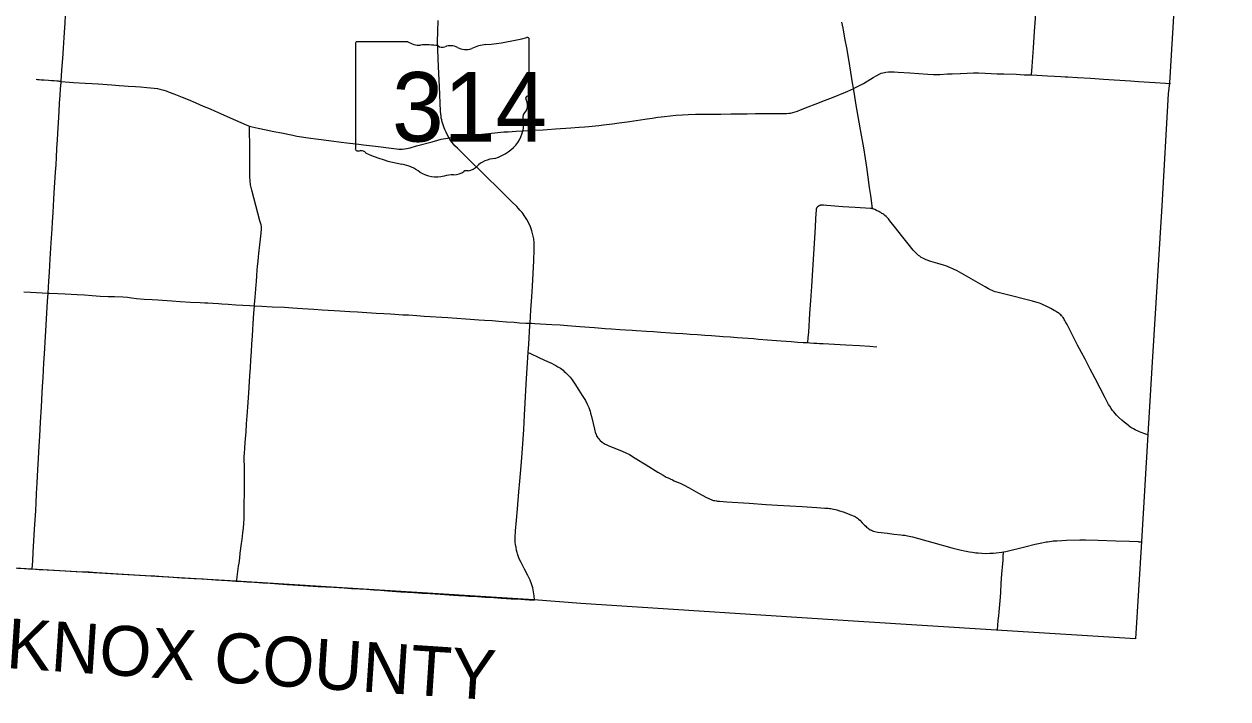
# Model space of a CAD drawing. Extents: x 9078 to 9739, y 4248 to 4966.
# Drawn here: x 9527 to 9647.5, y 4264.9 to 4332.5 of the extents above; entities that cross this region are included whole.
import ezdxf

# ---------------------------------------------------------------- set-up
doc = ezdxf.new("R2010")
doc.units = 0
for name, color, linetype in [('GM_X_Adjacent_County_Text', 7, 'Continuous'), ('GM_X_County', 7, 'Continuous'), ('GM_X_County_Road', 7, 'Continuous'), ('GM_X_State_Route', 7, 'Continuous'), ('GM_X_State_Shield', 7, 'Continuous'), ('GM_X_Township_Road', 7, 'Continuous')]:
    doc.layers.add(name, color=color, linetype=linetype)

msp = doc.modelspace()

# ---------------------------------------------------------------- linework, layer by layer
at = {"layer": 'GM_X_County'}
msp.add_lwpolyline([(9647.55, 4428.55), (9647.41, 4425.74), (9646.56, 4403.19), (9646.56, 4403.07), (9644.94, 4380.52), (9644.77, 4377.86), (9644.66, 4376.07), (9644.25, 4369.41), (9641.71, 4326.63), (9641.57, 4325.53), (9640.94, 4314.3), (9639.94, 4298.12), (9639.53, 4291.39), (9638.88, 4280.68), (9638.29, 4270.92), (9624.37, 4271.81), (9610.55, 4272.68), (9582.74, 4274.46), (9578.04, 4274.83), (9548.2, 4276.71), (9527.73, 4277.92), (9504.96, 4279.33)], dxfattribs=at)
at = {"layer": 'GM_X_County_Road'}
for points in [[(9627.89, 4327.41), (9627.95, 4328.25), (9628.07, 4330.13), (9628.17, 4331.76), (9628.26, 4333.07), (9628.3, 4333.81), (9628.36, 4334.79), (9628.44, 4336.1), (9628.53, 4337.65), (9628.58, 4338.47), (9628.64, 4339.36), (9628.72, 4340.67), (9628.83, 4342.39), (9628.9, 4343.7), (9628.96, 4344.76), (9629.07, 4346.31), (9629.14, 4347.38)], [(9530.7, 4326.77), (9530.74, 4327.4), (9530.8, 4328.29), (9530.86, 4329.07), (9530.92, 4330.09), (9530.99, 4331.16), (9531.03, 4331.65), (9531.1, 4332.63), (9531.15, 4333.37), (9531.19, 4334.11), (9531.22, 4334.59), (9531.28, 4335.82), (9531.33, 4336.64), (9531.36, 4337.29), (9531.38, 4337.7), (9531.39, 4337.88)], [(9610.05, 4326.04), (9610.59, 4326.33), (9611.04, 4326.57), (9612.02, 4327.16), (9612.38, 4327.36), (9612.68, 4327.51), (9612.83, 4327.58), (9612.98, 4327.63), (9613.14, 4327.67), (9613.3, 4327.7), (9613.55, 4327.73), (9613.79, 4327.73), (9614.12, 4327.73), (9614.53, 4327.7), (9615.68, 4327.62), (9616.58, 4327.55), (9617.48, 4327.49), (9618.06, 4327.46), (9618.41, 4327.45), (9618.71, 4327.46), (9619.45, 4327.51), (9619.94, 4327.53), (9620.73, 4327.57), (9620.76, 4327.57), (9621.42, 4327.6), (9622.08, 4327.61), (9622.57, 4327.61), (9623.22, 4327.59), (9624.45, 4327.54), (9625.11, 4327.52), (9626.34, 4327.48), (9627.15, 4327.44), (9627.89, 4327.41)], [(9627.89, 4327.41), (9629.47, 4327.33), (9630.19, 4327.29), (9630.8, 4327.26), (9631.24, 4327.23), (9631.51, 4327.22), (9632.48, 4327.16), (9633.78, 4327.09), (9635.09, 4327), (9637.78, 4326.83), (9638.59, 4326.77), (9640.27, 4326.67), (9641.3, 4326.59), (9641.79, 4326.55)], [(9529.39, 4305.57), (9529.48, 4306.77), (9529.53, 4307.67), (9529.61, 4308.98), (9529.7, 4310.59), (9529.79, 4312.01), (9529.83, 4312.67), (9529.89, 4313.65), (9529.93, 4314.3), (9529.97, 4314.96), (9530.01, 4315.61), (9530.14, 4317.66), (9530.19, 4318.4), (9530.23, 4319.13), (9530.28, 4320.03), (9530.34, 4320.93), (9530.4, 4322.16), (9530.42, 4322.57), (9530.46, 4323.22), (9530.49, 4323.71), (9530.54, 4324.62), (9530.59, 4325.35), (9530.64, 4326.01), (9530.69, 4326.66), (9530.7, 4326.77)], [(9601.7, 4323.55), (9602.27, 4323.55), (9603.01, 4323.54), (9603.33, 4323.55), (9603.58, 4323.58), (9603.74, 4323.6), (9603.98, 4323.65), (9604.21, 4323.72), (9604.44, 4323.79), (9604.75, 4323.91), (9605.51, 4324.22), (9606.2, 4324.48), (9607.14, 4324.85), (9607.96, 4325.17), (9609.26, 4325.69), (9610.03, 4326.03), (9610.05, 4326.04)], [(9569.54, 4321.12), (9569.83, 4321.16), (9570.1, 4321.19), (9572.83, 4321.47), (9574.14, 4321.61), (9575.04, 4321.7), (9575.45, 4321.73), (9576.27, 4321.77), (9578.07, 4321.87), (9578.97, 4321.93), (9579.38, 4321.95), (9580.2, 4322.01), (9581.75, 4322.12), (9582.57, 4322.17), (9583.14, 4322.22), (9583.55, 4322.26), (9584.53, 4322.35), (9585.02, 4322.4), (9585.92, 4322.52), (9586.57, 4322.61), (9587.38, 4322.73), (9588.27, 4322.86), (9589.16, 4323), (9589.9, 4323.1), (9590.46, 4323.18), (9591.12, 4323.26), (9591.69, 4323.33), (9592.26, 4323.39), (9592.91, 4323.43), (9593.49, 4323.46), (9594.23, 4323.49), (9595.29, 4323.5), (9595.95, 4323.5), (9596.77, 4323.5), (9597.75, 4323.52), (9599.4, 4323.53), (9600.22, 4323.55), (9600.95, 4323.55), (9601.7, 4323.55)], [(9526.97, 4305.69), (9527.64, 4305.66), (9528.23, 4305.63), (9528.79, 4305.6), (9529.39, 4305.57)], [(9527.79, 4277.93), (9527.85, 4278.7), (9527.9, 4279.6), (9528.04, 4281.89), (9528.15, 4283.77), (9528.19, 4284.51), (9528.24, 4285.49), (9528.3, 4286.56), (9528.37, 4287.87), (9528.43, 4289.01), (9528.5, 4290.24), (9528.56, 4291.24), (9528.64, 4292.62), (9528.73, 4294.17), (9528.81, 4295.56), (9528.84, 4296.22), (9528.9, 4297.12), (9528.94, 4297.85), (9528.98, 4298.59), (9529.03, 4299.49), (9529.14, 4301.21), (9529.18, 4301.78), (9529.2, 4302.36), (9529.27, 4303.58), (9529.34, 4304.73), (9529.39, 4305.55), (9529.39, 4305.57)], [(9529.39, 4305.57), (9529.54, 4305.56), (9530.35, 4305.53), (9531.1, 4305.49), (9532.3, 4305.42), (9533.04, 4305.38), (9533.81, 4305.33), (9534.59, 4305.27), (9535.4, 4305.23), (9536.03, 4305.21), (9536.88, 4305.18), (9537.35, 4305.14), (9537.73, 4305.09), (9538.25, 4305.03), (9539.02, 4304.96), (9539.82, 4304.92), (9540.39, 4304.88), (9541.32, 4304.83), (9541.77, 4304.8), (9542.61, 4304.73), (9543.66, 4304.66), (9544.61, 4304.62), (9545.08, 4304.6), (9545.4, 4304.57), (9545.88, 4304.54), (9546.46, 4304.51), (9546.79, 4304.49), (9547.42, 4304.44), (9548.2, 4304.4), (9548.88, 4304.36), (9549.58, 4304.32), (9550.06, 4304.29)], [(9550.06, 4304.29), (9550.78, 4304.25), (9551.82, 4304.2), (9553.06, 4304.14), (9553.88, 4304.09), (9554.86, 4304.02), (9556.01, 4303.94), (9556.83, 4303.9), (9558.03, 4303.83), (9558.61, 4303.79), (9559.62, 4303.72), (9560.36, 4303.67), (9562.26, 4303.56), (9563.01, 4303.51), (9563.68, 4303.47), (9564.11, 4303.44), (9564.93, 4303.4), (9565.5, 4303.37), (9566.32, 4303.31), (9567.06, 4303.26), (9569.43, 4303.11), (9571.23, 4302.98), (9572.54, 4302.9), (9573.11, 4302.86), (9573.85, 4302.81), (9574.52, 4302.76), (9575.31, 4302.69), (9576.06, 4302.64), (9576.61, 4302.59), (9577.22, 4302.55), (9577.66, 4302.54)], [(9577.48, 4299.6), (9577.63, 4299.53), (9578.6, 4299.09), (9579.42, 4298.7), (9579.79, 4298.53), (9580.03, 4298.41), (9580.25, 4298.3), (9580.34, 4298.25), (9580.45, 4298.19), (9580.58, 4298.11), (9580.7, 4298.03), (9580.84, 4297.94), (9580.96, 4297.83), (9581.09, 4297.72), (9581.21, 4297.61), (9581.42, 4297.4), (9581.66, 4297.14), (9581.77, 4297.01), (9581.87, 4296.88), (9582.15, 4296.48), (9582.55, 4295.85), (9582.89, 4295.3), (9583.2, 4294.81), (9583.39, 4294.45), (9583.48, 4294.24), (9583.55, 4294.09), (9583.61, 4293.91), (9583.67, 4293.72), (9583.72, 4293.52), (9583.8, 4293.2), (9584.1, 4291.93), (9584.14, 4291.76), (9584.19, 4291.62), (9584.27, 4291.39), (9584.32, 4291.28), (9584.38, 4291.17), (9584.45, 4291.07), (9584.53, 4290.96), (9584.61, 4290.87), (9584.68, 4290.79), (9584.87, 4290.63), (9585.07, 4290.5), (9585.18, 4290.43), (9585.29, 4290.38), (9585.47, 4290.3), (9585.73, 4290.2), (9586.64, 4289.84), (9587.17, 4289.6), (9587.61, 4289.38), (9588.17, 4289.04), (9589.29, 4288.35), (9590.47, 4287.62), (9590.99, 4287.31), (9591.29, 4287.14), (9591.48, 4287.05), (9591.68, 4286.95), (9591.91, 4286.84), (9592.1, 4286.76), (9592.31, 4286.67), (9592.53, 4286.58), (9592.75, 4286.48), (9593.02, 4286.34), (9593.6, 4286.04), (9594.54, 4285.53), (9595.33, 4285.09), (9595.55, 4284.98), (9595.7, 4284.92), (9595.81, 4284.87), (9595.92, 4284.83), (9596.04, 4284.8), (9596.16, 4284.77), (9596.32, 4284.75), (9596.43, 4284.73), (9596.62, 4284.71), (9597.38, 4284.64), (9599.59, 4284.51), (9601.31, 4284.39), (9602.45, 4284.32), (9604.9, 4284.17), (9606.38, 4284.08), (9607.18, 4284.03), (9607.5, 4284.01), (9607.66, 4283.99), (9607.78, 4283.97), (9607.91, 4283.95), (9608.04, 4283.92), (9608.24, 4283.88), (9608.39, 4283.84), (9608.65, 4283.75), (9609.01, 4283.64), (9609.63, 4283.41), (9609.84, 4283.33), (9610.01, 4283.25), (9610.12, 4283.21), (9610.24, 4283.14), (9610.34, 4283.08), (9610.44, 4283.01), (9610.55, 4282.93), (9610.7, 4282.8), (9610.93, 4282.56), (9611.15, 4282.32), (9611.27, 4282.21), (9611.36, 4282.12), (9611.44, 4282.06), (9611.51, 4282), (9611.58, 4281.95), (9611.73, 4281.86), (9611.84, 4281.8), (9611.95, 4281.75), (9612.06, 4281.71), (9612.18, 4281.68), (9612.5, 4281.62), (9613.46, 4281.5), (9614.09, 4281.43), (9614.79, 4281.36), (9614.99, 4281.33), (9615.18, 4281.31), (9615.47, 4281.25), (9615.95, 4281.14), (9618.01, 4280.57), (9619.91, 4280.04), (9620.7, 4279.83), (9621.34, 4279.7), (9621.67, 4279.64), (9621.98, 4279.6), (9622.31, 4279.56), (9622.55, 4279.53), (9622.89, 4279.51), (9623.29, 4279.49), (9623.7, 4279.5), (9623.88, 4279.5), (9624.07, 4279.51), (9624.35, 4279.53), (9624.91, 4279.61), (9625.06, 4279.64)], [(9625.06, 4279.64), (9625.31, 4279.69), (9627.22, 4280.16), (9628.25, 4280.41), (9628.56, 4280.47), (9628.9, 4280.55), (9629.21, 4280.61), (9629.34, 4280.63), (9629.49, 4280.66), (9629.7, 4280.69), (9629.9, 4280.71), (9630.06, 4280.73), (9630.41, 4280.76), (9630.9, 4280.79), (9631.39, 4280.8), (9632.71, 4280.85), (9633.27, 4280.84), (9634.54, 4280.8), (9636.31, 4280.74), (9637.7, 4280.7), (9638.55, 4280.67), (9638.64, 4280.66), (9638.76, 4280.66), (9638.92, 4280.65)], [(9526.37, 4278.01), (9527.03, 4277.98), (9527.44, 4277.95), (9527.79, 4277.93)]]:
    msp.add_lwpolyline(points, dxfattribs=at)
at = {"layer": 'GM_X_State_Route'}
msp.add_lwpolyline([(9578.09, 4274.82), (9578.06, 4275.23), (9578.01, 4275.64), (9577.93, 4276.04), (9577.8, 4276.43), (9577.66, 4276.82), (9577.45, 4277.26), (9577.1, 4277.92), (9576.76, 4278.57), (9576.64, 4278.82), (9576.55, 4279.04), (9576.47, 4279.26), (9576.41, 4279.44), (9576.36, 4279.59), (9576.31, 4279.79), (9576.25, 4280.1), (9576.23, 4280.22), (9576.2, 4280.39), (9576.18, 4280.57), (9576.17, 4280.76), (9576.16, 4281.09), (9576.2, 4281.74), (9576.3, 4282.8), (9576.4, 4283.94), (9576.54, 4285.65), (9576.64, 4286.71), (9576.77, 4288.26), (9576.82, 4289.08), (9577.02, 4291.86), (9577.1, 4293.33), (9577.18, 4294.56), (9577.28, 4296.44), (9577.38, 4298.08), (9577.48, 4299.6), (9577.54, 4300.45), (9577.65, 4302.33), (9577.66, 4302.54), (9577.75, 4303.89), (9577.82, 4305.2), (9577.89, 4306.25), (9578.03, 4308.79), (9578.07, 4309.94), (9578.07, 4310.59), (9578.02, 4311), (9577.94, 4311.41), (9577.84, 4311.8), (9577.7, 4312.19), (9577.53, 4312.57), (9577.34, 4312.93), (9577.07, 4313.35), (9576.97, 4313.5), (9576.86, 4313.65), (9576.65, 4313.88), (9576.5, 4314.05), (9576.33, 4314.24), (9575.81, 4314.75), (9575.11, 4315.44), (9574.29, 4316.24), (9573.46, 4317.04), (9571.01, 4319.45), (9570.38, 4320.07), (9570.14, 4320.32), (9569.87, 4320.63), (9569.63, 4320.96), (9569.54, 4321.12), (9569.46, 4321.24), (9569.24, 4321.68), (9569.11, 4321.95), (9569.04, 4322.13), (9568.98, 4322.32), (9568.91, 4322.51), (9568.86, 4322.7), (9568.81, 4322.91), (9568.77, 4323.1), (9568.75, 4323.31), (9568.73, 4323.48), (9568.7, 4323.8), (9568.58, 4326.25), (9568.49, 4328.22), (9568.42, 4329.94), (9568.4, 4330.76), (9568.43, 4331.74), (9568.46, 4332.88)], dxfattribs=at)
at = {"layer": 'GM_X_State_Shield'}
for p, q in [((9565.42, 4330.74), (9560.33, 4330.74)), ((9577.56, 4325.47), (9577.56, 4331)), ((9560.16, 4330.56), (9560.16, 4319.99)), ((9577.56, 4325.47), (9577.56, 4325.47))]:
    msp.add_line(p, q, dxfattribs=at)
for centre, major_axis, start_param, end_param in [((9560.36, 4330.58), (0.202, 0), 1.712693, 3.28349), ((9566.64, 4331.96), (1.96, 0), 4.042523, 4.731795), ((9571.36, 4345.14), (18.45, 0), 4.814394, 5.042369), ((9577.37, 4331.02), (0.194, 0), 6.141152, 7.989035), ((9567.29, 4324.81), (7.02, 0), 1.404758, 1.657858), ((9568.88, 4330.63), (0.564, 0), 3.836095, 5.185415), ((9569.71, 4329.41), (1.17, 0), 0.950623, 2.079405), ((9571.22, 4331.09), (1.41, 0), 4.081561, 5.145723), ((9573.71, 4327.51), (3.71, 0), 1.699011, 2.107814), ((9577.51, 4325.07), (0.3, 0), 1.883978, 3.671073), ((9575.61, 4324.37), (1.8, 0), 5.934695, 6.695948), ((9577.35, 4325.45), (0.207, 0), 5.05454, 6.418171), ((9578.25, 4323.16), (1.31, 0), 2.387724, 3.262537), ((9572.39, 4322.46), (4.62, 0), 5.101752, 6.440018), ((9560.36, 4319.97), (0.203, 0), 3.00124, 4.508301), ((9560.39, 4321.05), (1.55, 0), 4.665946, 4.897461), ((9560.71, 4319.38), (0.56, 0), 0.519207, 1.627899), ((9567.77, 4328.87), (13.33, 0), 4.195997, 4.488961), ((9574.34, 4317.02), (2.53, 0), 1.647645, 2.488434), ((9563.8, 4315.24), (4.17, 0), 0.823519, 1.323587), ((9568.31, 4319.33), (2.65, 0), 4.026481, 4.996735), ((9569.84, 4315.67), (2.17, 0), 1.495662, 1.94098), ((9570.03, 4318.54), (1.41, 0), 4.691044, 5.507374), ((9571.31, 4317.51), (0.397, 0), 1.147584, 2.315152), ((9571.14, 4318.97), (1.49, 0), 4.937069, 5.64225)]:
    msp.add_ellipse(centre, major_axis=major_axis, ratio=0.8, start_param=start_param, end_param=end_param, dxfattribs=at)
at = {"layer": 'GM_X_Township_Road'}
for points in [[(9610.05, 4326.04), (9610.04, 4326.08), (9609.94, 4326.61), (9609.6, 4328.75), (9609.37, 4330.13), (9609.23, 4330.94), (9609.06, 4331.91), (9609.03, 4332.1), (9608.96, 4332.39), (9608.87, 4332.69)], [(9528.2, 4326.98), (9528.33, 4326.96)], [(9528.33, 4326.96), (9528.36, 4326.96), (9528.5, 4326.95), (9528.69, 4326.93), (9529, 4326.92), (9529.44, 4326.89), (9529.74, 4326.87), (9529.99, 4326.85), (9530.26, 4326.82), (9530.4, 4326.81), (9530.51, 4326.8), (9530.6, 4326.79), (9530.65, 4326.78), (9530.7, 4326.77)], [(9530.7, 4326.77), (9531.94, 4326.66), (9533.09, 4326.59), (9533.82, 4326.55), (9534.39, 4326.51), (9535.78, 4326.41), (9536.51, 4326.36), (9537, 4326.33), (9537.41, 4326.3), (9538.14, 4326.25), (9538.63, 4326.21), (9539.29, 4326.15), (9540.02, 4326.08), (9540.35, 4326.04), (9540.59, 4325.99), (9540.99, 4325.89), (9541.22, 4325.82), (9541.53, 4325.7), (9541.99, 4325.52), (9542.82, 4325.18), (9543.43, 4324.94), (9544.18, 4324.62), (9544.93, 4324.29), (9545.61, 4324.01), (9546.06, 4323.82), (9546.96, 4323.42), (9547.64, 4323.12), (9548.68, 4322.65), (9549.22, 4322.42), (9549.55, 4322.28)], [(9611.96, 4314.03), (9611.77, 4315.33), (9611.66, 4316.14), (9611.52, 4317.19), (9611.39, 4318.17), (9611.25, 4319.06), (9611.07, 4320.11), (9610.73, 4322.13), (9610.33, 4324.39), (9610.11, 4325.68), (9610.05, 4326.04)], [(9549.61, 4317.46), (9549.6, 4317.95), (9549.61, 4318.6), (9549.6, 4319.56), (9549.59, 4320.6), (9549.56, 4321.56), (9549.55, 4322.28)], [(9549.55, 4322.28), (9549.84, 4322.22), (9550.44, 4322.09), (9551.23, 4321.91), (9552, 4321.75), (9552.76, 4321.6), (9553.89, 4321.37), (9554.29, 4321.29), (9554.78, 4321.21), (9555.42, 4321.12), (9556.48, 4320.98), (9557.78, 4320.8), (9558.75, 4320.69), (9559.32, 4320.61), (9559.92, 4320.54), (9560.52, 4320.47), (9560.99, 4320.41), (9561.87, 4320.31), (9562.74, 4320.21), (9563.23, 4320.15), (9564.28, 4320), (9564.52, 4319.98), (9564.69, 4319.97), (9564.85, 4319.98), (9565.09, 4320), (9565.33, 4320.05), (9565.65, 4320.12), (9566.28, 4320.3), (9567.86, 4320.72), (9568.41, 4320.88), (9568.76, 4320.97), (9568.96, 4321.01), (9569.18, 4321.06), (9569.38, 4321.09), (9569.54, 4321.12)], [(9550.23, 4306.41), (9550.25, 4306.7), (9550.29, 4307.32), (9550.34, 4307.85), (9550.37, 4308.26), (9550.42, 4308.76), (9550.46, 4309.18), (9550.49, 4309.53), (9550.58, 4310.41), (9550.66, 4310.98), (9550.73, 4311.55), (9550.77, 4311.99), (9550.77, 4312.19), (9550.73, 4312.41), (9550.61, 4312.8), (9550.39, 4313.56), (9549.8, 4315.86), (9549.66, 4316.42), (9549.61, 4317.2), (9549.61, 4317.28), (9549.61, 4317.46)], [(9605.47, 4300.6), (9605.52, 4301.08), (9605.56, 4301.65), (9605.68, 4303.53), (9605.76, 4304.83), (9605.86, 4306.22), (9606, 4308.42), (9606.2, 4311.6), (9606.31, 4313.57), (9606.33, 4313.79), (9606.34, 4313.86), (9606.34, 4313.95), (9606.35, 4314), (9606.36, 4314.03), (9606.37, 4314.07), (9606.38, 4314.1), (9606.4, 4314.13), (9606.42, 4314.17), (9606.45, 4314.21), (9606.47, 4314.23), (9606.5, 4314.26), (9606.53, 4314.28), (9606.57, 4314.3), (9606.6, 4314.33), (9606.64, 4314.34), (9606.68, 4314.36), (9606.72, 4314.37), (9606.75, 4314.38), (9606.79, 4314.39), (9606.84, 4314.39), (9606.88, 4314.39), (9606.94, 4314.39), (9607.04, 4314.39), (9607.37, 4314.37), (9608.99, 4314.24), (9609.57, 4314.2), (9610.22, 4314.16), (9611.76, 4314.06), (9611.82, 4314.06), (9611.88, 4314.05), (9611.96, 4314.03)], [(9639.59, 4291.32), (9639.21, 4291.46), (9638.86, 4291.59), (9638.68, 4291.67), (9638.25, 4291.87), (9638.1, 4291.95), (9637.95, 4292.03), (9637.83, 4292.11), (9637.7, 4292.19), (9637.61, 4292.26), (9637.41, 4292.42), (9637.16, 4292.64), (9636.91, 4292.85), (9636.59, 4293.15), (9636.38, 4293.35), (9636.24, 4293.51), (9636.11, 4293.66), (9635.99, 4293.8), (9635.86, 4293.99), (9635.72, 4294.22), (9635.6, 4294.41), (9635.25, 4295.06), (9634.25, 4297), (9633.76, 4297.95), (9633.24, 4298.96), (9632.89, 4299.61), (9632.49, 4300.36), (9632.1, 4301.08), (9631.44, 4302.4), (9631.29, 4302.69), (9631.22, 4302.82), (9631.16, 4302.92), (9631.1, 4303.01), (9631.03, 4303.11), (9630.98, 4303.17), (9630.93, 4303.24), (9630.88, 4303.29), (9630.8, 4303.37), (9630.72, 4303.44), (9630.63, 4303.51), (9630.55, 4303.57), (9630.47, 4303.63), (9630.29, 4303.74), (9630.16, 4303.82), (9629.8, 4304.03), (9629.48, 4304.19), (9629.29, 4304.29), (9629.06, 4304.39), (9628.84, 4304.49), (9628.67, 4304.55), (9628.45, 4304.63), (9628.32, 4304.66), (9627.98, 4304.76), (9625.19, 4305.45), (9624.39, 4305.65), (9624.22, 4305.7), (9624.08, 4305.75), (9623.92, 4305.82), (9623.78, 4305.88), (9623.56, 4305.99), (9623.39, 4306.09), (9623.25, 4306.18), (9622.99, 4306.33), (9622.78, 4306.45), (9622.08, 4306.86), (9620.42, 4307.78), (9620.06, 4307.96), (9619.77, 4308.1), (9619.53, 4308.19), (9619.29, 4308.28), (9619.07, 4308.36), (9618.51, 4308.51), (9617.8, 4308.72), (9617.34, 4308.89), (9617.12, 4308.99), (9616.98, 4309.06), (9616.83, 4309.14), (9616.68, 4309.25), (9616.56, 4309.33), (9616.43, 4309.45), (9616.32, 4309.55), (9616.04, 4309.85), (9615.52, 4310.49), (9614.86, 4311.32), (9614.26, 4312.1), (9613.7, 4312.81), (9613.55, 4312.99), (9613.43, 4313.12), (9613.31, 4313.23), (9613.19, 4313.34), (9613.09, 4313.42), (9612.99, 4313.49), (9612.9, 4313.55), (9612.79, 4313.62), (9612.69, 4313.67), (9612.6, 4313.73), (9612.36, 4313.85), (9612.2, 4313.93), (9612.1, 4313.98), (9612.03, 4314.01), (9611.96, 4314.03)], [(9550.06, 4304.29), (9550.07, 4304.41), (9550.13, 4305.15), (9550.19, 4305.96), (9550.23, 4306.41)], [(9549.02, 4284.23), (9549.02, 4284.25), (9549.05, 4285.72), (9549.07, 4286.71), (9549.06, 4287.31), (9549.06, 4287.85), (9549.05, 4288.33), (9549.03, 4288.76), (9549.04, 4288.97), (9549.04, 4289.27), (9549.05, 4289.44), (9549.1, 4290.09), (9549.17, 4290.99), (9549.22, 4291.64), (9549.27, 4292.46), (9549.32, 4293.28), (9549.35, 4293.69), (9549.39, 4294.18), (9549.42, 4294.59), (9549.49, 4295.57), (9549.53, 4296.14), (9549.61, 4297.29), (9549.66, 4298.11), (9549.71, 4298.84), (9549.76, 4299.71), (9549.8, 4300.46), (9549.85, 4301.28), (9549.9, 4301.93), (9549.93, 4302.52), (9550, 4303.54), (9550.06, 4304.29)], [(9577.66, 4302.54), (9577.81, 4302.54), (9578.13, 4302.53), (9578.71, 4302.49), (9579.85, 4302.42), (9580.67, 4302.37), (9581.41, 4302.31), (9582.64, 4302.22), (9584.11, 4302.11), (9585.17, 4302.03), (9585.83, 4301.98), (9586.65, 4301.92), (9587.22, 4301.88), (9587.88, 4301.84), (9588.28, 4301.82), (9589.33, 4301.74), (9590.03, 4301.7), (9590.76, 4301.65), (9591.73, 4301.58), (9592.22, 4301.55), (9592.96, 4301.5), (9593.37, 4301.47), (9593.69, 4301.45), (9594.43, 4301.4), (9595.17, 4301.35), (9595.82, 4301.31), (9596.63, 4301.26), (9597.01, 4301.23), (9597.73, 4301.18), (9598.39, 4301.13), (9600.02, 4301), (9600.55, 4300.96), (9601.42, 4300.89), (9602.81, 4300.79), (9603.79, 4300.71), (9604.46, 4300.66), (9605.02, 4300.62), (9605.47, 4300.6)], [(9605.47, 4300.6), (9605.66, 4300.58), (9606.08, 4300.56), (9606.38, 4300.53), (9606.66, 4300.52), (9607, 4300.5), (9609.29, 4300.39), (9610.64, 4300.3), (9611.67, 4300.23), (9612.37, 4300.18)], [(9548.51, 4278.51), (9548.58, 4279.02), (9548.64, 4279.51), (9548.77, 4280.48), (9548.82, 4280.89), (9548.9, 4281.54), (9548.95, 4282.03), (9549, 4282.52), (9549.02, 4282.93), (9549.03, 4283.34), (9549.02, 4283.59), (9549.02, 4284.23)], [(9624.46, 4271.82), (9624.55, 4272.76), (9624.59, 4273.23), (9624.64, 4273.64), (9624.76, 4275.09), (9624.8, 4275.61), (9624.82, 4275.84), (9624.84, 4276.24), (9624.85, 4276.5), (9624.91, 4277.4), (9625, 4278.46), (9625.03, 4278.76), (9625.05, 4279.12), (9625.05, 4279.25), (9625.06, 4279.53), (9625.06, 4279.64)], [(9527.79, 4277.93), (9528.48, 4277.89), (9529.29, 4277.84), (9530.52, 4277.78), (9532.19, 4277.69), (9532.93, 4277.65), (9533.5, 4277.63), (9534.28, 4277.57), (9534.8, 4277.54), (9536.41, 4277.44), (9538.05, 4277.35), (9539.19, 4277.28), (9540.09, 4277.23), (9540.91, 4277.18), (9541.49, 4277.14), (9542.79, 4277.05), (9543.45, 4277.02), (9544.02, 4276.98), (9544.92, 4276.93), (9546.14, 4276.85), (9547.37, 4276.77), (9548.19, 4276.71), (9548.27, 4276.7)], [(9548.27, 4276.7), (9548.29, 4276.82), (9548.34, 4277.15), (9548.47, 4278.21), (9548.51, 4278.51)], [(9548.27, 4276.7), (9548.6, 4276.69), (9549.33, 4276.64), (9550.07, 4276.6), (9550.89, 4276.55), (9551.62, 4276.49), (9552.48, 4276.44), (9553.34, 4276.38), (9554.44, 4276.3), (9555.45, 4276.24), (9556.45, 4276.18), (9557.98, 4276.09), (9559.04, 4276.03), (9559.77, 4275.98), (9560.58, 4275.93), (9561.28, 4275.89), (9562.01, 4275.83), (9562.67, 4275.79), (9563.4, 4275.74), (9564.71, 4275.65), (9566.02, 4275.57), (9566.84, 4275.52), (9567.66, 4275.46), (9568.15, 4275.43), (9568.64, 4275.4), (9569.13, 4275.38), (9569.54, 4275.35), (9570.03, 4275.32), (9570.52, 4275.28), (9570.85, 4275.26), (9571.5, 4275.22), (9572.4, 4275.16), (9573.2, 4275.1), (9574.04, 4275.06), (9574.81, 4275.01), (9575.76, 4274.95), (9576.33, 4274.92), (9577.15, 4274.87), (9577.56, 4274.84), (9578.09, 4274.82)]]:
    msp.add_lwpolyline(points, dxfattribs=at)

# ---------------------------------------------------------------- texts
at = {"layer": 'GM_X_Adjacent_County_Text'}
msp.add_text('KNOX COUNTY', height=5, rotation=356.2231, dxfattribs=at).set_placement((9525.12, 4268.01))
at = {"layer": 'GM_X_State_Shield'}
msp.add_text('314', height=6.961, dxfattribs=at).set_placement((9563.83, 4320.74))

doc.saveas('drawing.dxf')
